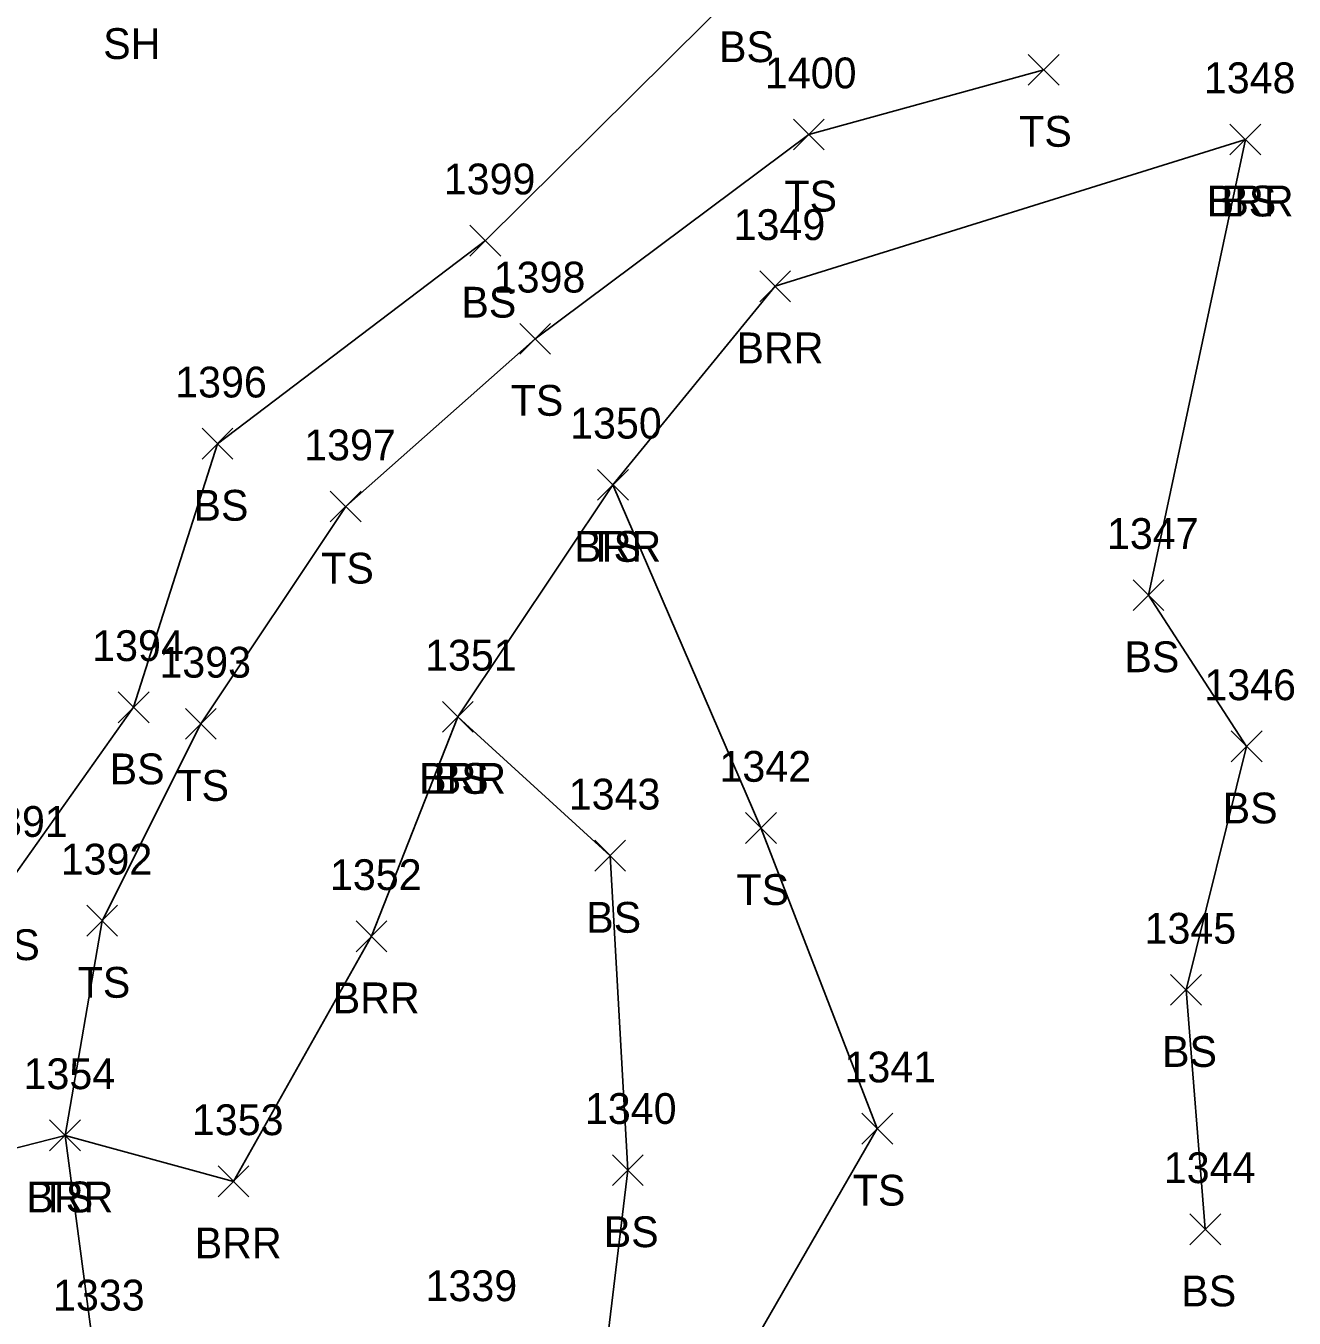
# Model space of a CAD drawing. Extents: x 1501299 to 1502485, y 381423 to 383765.
# Drawn here: x 1501750.2 to 1501832.6, y 383170.2 to 383254.1 of the extents above; entities that cross this region are included whole.
import ezdxf

# ---------------------------------------------------------------- set-up
doc = ezdxf.new("R2010")
doc.units = 0
for name, color, linetype in [('L_A', 7, 'Continuous'), ('L_I', 7, 'Continuous'), ('L_TIC', 7, 'Continuous'), ('LABL', 7, 'Continuous'), ('LELB', 7, 'Continuous')]:
    doc.layers.add(name, color=color, linetype=linetype)

msp = doc.modelspace()

# ---------------------------------------------------------------- linework, layer by layer
at = {"layer": 'L_TIC'}
for points in [[(1501815.316, 383250.234), (1501817.316, 383252.234)], [(1501817.316, 383250.234), (1501815.316, 383252.234)], [(1501800.073, 383246.027), (1501802.073, 383248.027)], [(1501802.073, 383246.027), (1501800.073, 383248.027)], [(1501828.407, 383245.711), (1501830.407, 383247.711)], [(1501830.407, 383245.711), (1501828.407, 383247.711)], [(1501828.407, 383245.711), (1501830.407, 383247.711)], [(1501830.407, 383245.711), (1501828.407, 383247.711)], [(1501779.065, 383239.141), (1501781.065, 383241.141)], [(1501781.065, 383239.141), (1501779.065, 383241.141)], [(1501797.883, 383236.177), (1501799.883, 383238.177)], [(1501799.883, 383236.177), (1501797.883, 383238.177)], [(1501782.301, 383232.77), (1501784.301, 383234.77)], [(1501784.301, 383232.77), (1501782.301, 383234.77)], [(1501761.675, 383225.957), (1501763.675, 383227.957)], [(1501763.675, 383225.957), (1501761.675, 383227.957)], [(1501787.348, 383223.288), (1501789.348, 383225.288)], [(1501789.348, 383223.288), (1501787.348, 383225.288)], [(1501787.348, 383223.288), (1501789.348, 383225.288)], [(1501789.348, 383223.288), (1501787.348, 383225.288)], [(1501769.997, 383221.876), (1501771.997, 383223.876)], [(1501771.997, 383221.876), (1501769.997, 383223.876)], [(1501822.115, 383216.122), (1501824.115, 383218.122)], [(1501824.115, 383216.122), (1501822.115, 383218.122)], [(1501756.23, 383208.844), (1501758.23, 383210.844)], [(1501758.23, 383208.844), (1501756.23, 383210.844)], [(1501760.593, 383207.768), (1501762.593, 383209.768)], [(1501762.593, 383207.768), (1501760.593, 383209.768)], [(1501777.275, 383208.226), (1501779.275, 383210.226)], [(1501779.275, 383208.226), (1501777.275, 383210.226)], [(1501777.275, 383208.226), (1501779.275, 383210.226)], [(1501779.275, 383208.226), (1501777.275, 383210.226)], [(1501828.492, 383206.305), (1501830.492, 383208.305)], [(1501830.492, 383206.305), (1501828.492, 383208.305)], [(1501796.958, 383201.009), (1501798.958, 383203.009)], [(1501798.958, 383201.009), (1501796.958, 383203.009)], [(1501787.171, 383199.207), (1501789.171, 383201.207)], [(1501789.171, 383199.207), (1501787.171, 383201.207)], [(1501754.187, 383194.987), (1501756.187, 383196.987)], [(1501756.187, 383194.987), (1501754.187, 383196.987)], [(1501771.667, 383193.977), (1501773.667, 383195.977)], [(1501773.667, 383193.977), (1501771.667, 383195.977)], [(1501824.558, 383190.496), (1501826.558, 383192.496)], [(1501826.558, 383190.496), (1501824.558, 383192.496)], [(1501804.51, 383181.492), (1501806.51, 383183.492)], [(1501806.51, 383181.492), (1501804.51, 383183.492)], [(1501751.776, 383181.053), (1501753.776, 383183.053)], [(1501753.776, 383181.053), (1501751.776, 383183.053)], [(1501751.776, 383181.053), (1501753.776, 383183.053)], [(1501753.776, 383181.053), (1501751.776, 383183.053)], [(1501762.707, 383178.067), (1501764.707, 383180.067)], [(1501764.707, 383178.067), (1501762.707, 383180.067)], [(1501788.311, 383178.795), (1501790.311, 383180.795)], [(1501790.311, 383178.795), (1501788.311, 383180.795)], [(1501825.806, 383174.953), (1501827.806, 383176.953)], [(1501827.806, 383174.953), (1501825.806, 383176.953)]]:
    msp.add_lwpolyline(points, dxfattribs=at)
at = {"layer": 'LABL'}
msp.add_lwpolyline([(1501829.407, 383246.711), (1501798.883, 383237.177), (1501788.348, 383224.288), (1501778.275, 383209.226), (1501772.667, 383194.977), (1501763.707, 383179.067), (1501752.776, 383182.053), (1501739.644, 383178.686), (1501728.83, 383174.545), (1501722.4, 383185.429), (1501706.813, 383211.569)], dxfattribs=at)
at = {"layer": 'LELB'}
for points in [[(1501744.066, 383157.494), (1501739.644, 383178.686), (1501749.13, 383198.431), (1501757.23, 383209.844), (1501762.675, 383226.957), (1501780.065, 383240.141), (1501796.792, 383256.727)], [(1501744.066, 383157.494), (1501754.689, 383167.681), (1501752.776, 383182.053), (1501755.187, 383195.987), (1501761.593, 383208.768), (1501770.997, 383222.876), (1501783.301, 383233.77), (1501801.073, 383247.027), (1501816.316, 383251.234)], [(1501826.806, 383175.953), (1501825.558, 383191.496), (1501829.492, 383207.305), (1501823.115, 383217.122), (1501829.407, 383246.711)], [(1501772.599, 383144.108), (1501793.941, 383162.438), (1501805.51, 383182.492), (1501797.958, 383202.009), (1501788.348, 383224.288)], [(1501765.347, 383144.61), (1501787.488, 383164.69), (1501789.311, 383179.795), (1501788.171, 383200.207), (1501778.275, 383209.226)]]:
    msp.add_lwpolyline(points, dxfattribs=at)

# ---------------------------------------------------------------- texts
at = {"layer": 'L_A'}
for s, p in [('SH', (1501755.253, 383251.931)), ('BS', (1501795.233, 383251.727)), ('BS', (1501795.233, 383251.727)), ('TS', (1501814.725, 383246.234)), ('TS', (1501799.482, 383242.027)), ('BRR', (1501826.896, 383241.711)), ('BS', (1501827.848, 383241.711)), ('BS', (1501778.506, 383235.141)), ('BRR', (1501796.371, 383232.177)), ('TS', (1501781.711, 383228.77)), ('BS', (1501761.116, 383221.957)), ('BRR', (1501785.836, 383219.288)), ('TS', (1501786.757, 383219.288)), ('TS', (1501769.407, 383217.876)), ('BS', (1501821.556, 383212.122)), ('BS', (1501755.671, 383204.844)), ('BRR', (1501775.763, 383204.226)), ('BS', (1501776.716, 383204.226)), ('TS', (1501760.003, 383203.768)), ('BS', (1501827.933, 383202.305)), ('TS', (1501796.367, 383197.009)), ('BS', (1501786.612, 383195.207)), ('BS', (1501747.571, 383193.431)), ('TS', (1501753.596, 383190.987)), ('BRR', (1501770.155, 383189.977)), ('BS', (1501823.999, 383186.496)), ('TS', (1501803.919, 383177.492)), ('BRR', (1501750.264, 383177.053)), ('TS', (1501751.186, 383177.053)), ('BS', (1501787.751, 383174.795)), ('BRR', (1501761.195, 383174.067)), ('BS', (1501825.247, 383170.953))]:
    msp.add_text(s, height=2, dxfattribs=at).set_placement(p)
at = {"layer": 'L_I'}
for s, p in [('1400', (1501798.215, 383250.027)), ('1348', (1501826.715, 383249.711)), ('1348', (1501826.715, 383249.711)), ('1399', (1501777.365, 383243.141)), ('1349', (1501796.183, 383240.177)), ('1398', (1501780.609, 383236.77)), ('1396', (1501759.927, 383229.957)), ('1350', (1501785.569, 383227.288)), ('1350', (1501785.569, 383227.288)), ('1397', (1501768.304, 383225.876)), ('1347', (1501820.422, 383220.122)), ('1394', (1501754.538, 383212.844)), ('1393', (1501758.901, 383211.768)), ('1351', (1501776.149, 383212.226)), ('1351', (1501776.149, 383212.226)), ('1346', (1501826.745, 383210.305)), ('1342', (1501795.265, 383205.009)), ('1343', (1501785.479, 383203.207)), ('1391', (1501747.004, 383201.431)), ('1392', (1501752.494, 383198.987)), ('1352', (1501769.975, 383197.977)), ('1345', (1501822.865, 383194.496)), ('1354', (1501750.083, 383185.053)), ('1354', (1501750.083, 383185.053)), ('1341', (1501803.384, 383185.492)), ('1340', (1501786.531, 383182.795)), ('1353', (1501761.014, 383182.067)), ('1344', (1501824.114, 383178.953)), ('1339', (1501776.18, 383171.29)), ('1339', (1501776.18, 383171.29)), ('1333', (1501751.996, 383170.681)), ('1333', (1501751.996, 383170.681))]:
    msp.add_text(s, height=2, dxfattribs=at).set_placement(p)

doc.saveas('drawing.dxf')
